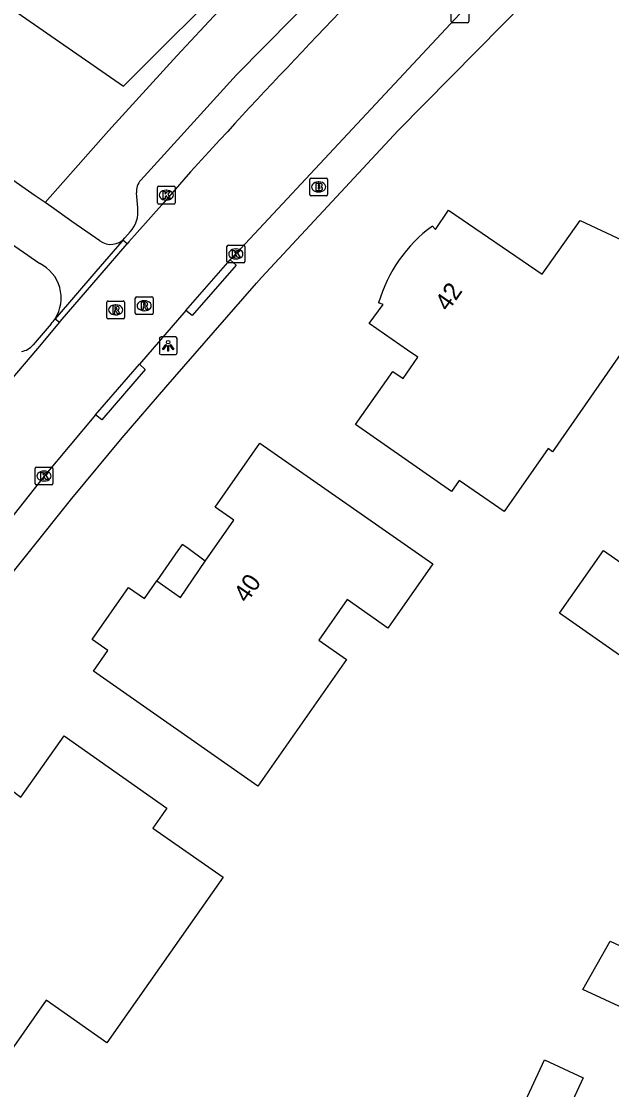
# Model space of a CAD drawing. Extents: x 158838 to 160074, y 386376 to 387776.
# Drawn here: x 159346.7 to 159380, y 386786.4 to 386846.6 of the extents above; entities that cross this region are included whole.
import ezdxf

# ---------------------------------------------------------------- set-up
doc = ezdxf.new("R2010")
doc.units = 0
for name, color, linetype in [('IMGEO_Brandkraan', 7, 'Continuous'), ('IMGEO_Kolk', 7, 'Continuous'), ('IMGEO_Lichtpunt', 7, 'Continuous'), ('IMGEO_Loofbos', 7, 'Continuous'), ('IMGEO_Muur', 7, 'Continuous'), ('IMGEO_Pand', 7, 'Continuous'), ('IMGEO_Pand_nummerreeks', 7, 'Continuous'), ('IMGEO_Pand_overbouw', 7, 'Continuous'), ('IMGEO_Rijbaan_lokaal_gesloten', 7, 'Continuous'), ('IMGEO_Rijbaan_lokaal_open', 7, 'Continuous'), ('IMGEO_Rioolput', 7, 'Continuous'), ('IMGEO_Voetpad_open', 7, 'Continuous')]:
    doc.layers.add(name, color=color, linetype=linetype)

msp = doc.modelspace()

# ---------------------------------------------------------------- linework, layer by layer
at = {"layer": 'IMGEO_Brandkraan'}
for p, q in [((159362.987, 386836.864), (159362.987, 386837.716)), ((159363.062, 386837.79), (159363.914, 386837.79)), ((159363.475, 386837.57), (159363.5, 386837.57)), ((159363.988, 386837.716), (159363.988, 386836.864)), ((159363.498, 386837.01), (159363.473, 386837.01)), ((159363.914, 386836.79), (159363.062, 386836.79))]:
    msp.add_line(p, q, dxfattribs=at)
for points in [[(159362.987, 386836.864), (159362.987, 386837.716)], [(159363.062, 386837.79), (159363.914, 386837.79)], [(159363.335, 386837.49), (159363.335, 386837.09), (159363.548, 386837.09)], [(159363.566, 386837.49), (159363.335, 386837.49)], [(159363.988, 386837.716), (159363.988, 386836.864)], [(159363.514, 386837.409), (159363.46, 386837.409), (159363.46, 386837.333)], [(159363.46, 386837.333), (159363.513, 386837.333)], [(159363.522, 386837.257), (159363.46, 386837.257), (159363.46, 386837.176)], [(159363.46, 386837.176), (159363.522, 386837.176)], [(159363.914, 386836.79), (159363.062, 386836.79)]]:
    msp.add_lwpolyline(points, dxfattribs=at)
for centre, radius, start, end in [((159363.064, 386837.714), 0.0765, 91.55205, 178.44795), ((159363.064, 386837.714), 0.0765, 91.55205, 178.44795), ((159363.57, 386837.345), 0.145, 59.4692, 91.53667), ((159363.595, 386837.392), 0.0922, 285.51372, 58.15012), ((159363.912, 386837.714), 0.0765, 1.55205, 88.44795), ((159363.912, 386837.714), 0.0765, 1.55205, 88.44795), ((159363.064, 386836.866), 0.0765, 181.55205, 268.44795), ((159363.064, 386836.866), 0.0765, 181.55205, 268.44795), ((159363.515, 386837.371), 0.0379, 267.82845, 90.93552), ((159363.523, 386837.216), 0.0404, 269.87594, 90.50774), ((159363.554, 386837.341), 0.251, 268.66757, 293.53466), ((159363.6, 386837.2), 0.105, 301.31148, 78.98903), ((159363.912, 386836.866), 0.0765, 271.55205, 358.44795), ((159363.912, 386836.866), 0.0765, 271.55205, 358.44795)]:
    msp.add_arc(centre, radius, start, end, dxfattribs=at)
for centre, major_axis, ratio, start_param, end_param in [((159363.474, 386837.29), (-0.387, 0.002), 0.722429, 4.712389, 7.853982), ((159363.499, 386837.29), (-0.39, 0.002), 0.717154, 1.570796, 4.712389)]:
    msp.add_ellipse(centre, major_axis=major_axis, ratio=ratio, start_param=start_param, end_param=end_param, dxfattribs=at)
at = {"layer": 'IMGEO_Kolk'}
for p, q in [((159370.953, 386846.626), (159370.953, 386847.478)), ((159371.954, 386847.478), (159371.954, 386846.626)), ((159371.88, 386846.552), (159371.028, 386846.552)), ((159354.395, 386836.402), (159354.395, 386837.254)), ((159354.47, 386837.328), (159355.322, 386837.328)), ((159354.883, 386837.108), (159354.908, 386837.108)), ((159355.396, 386837.254), (159355.396, 386836.402)), ((159355.322, 386836.328), (159354.47, 386836.328)), ((159354.906, 386836.548), (159354.881, 386836.548)), ((159358.319, 386833.089), (159358.319, 386833.941)), ((159358.394, 386834.015), (159359.246, 386834.015)), ((159359.32, 386833.941), (159359.32, 386833.089)), ((159358.83, 386833.235), (159358.805, 386833.235)), ((159358.807, 386833.795), (159358.832, 386833.795)), ((159359.246, 386833.015), (159358.394, 386833.015)), ((159347.51, 386820.564), (159347.51, 386821.416)), ((159347.585, 386821.49), (159348.437, 386821.49)), ((159347.998, 386821.27), (159348.023, 386821.27)), ((159348.511, 386821.416), (159348.511, 386820.564)), ((159348.021, 386820.71), (159347.996, 386820.71)), ((159348.437, 386820.49), (159347.585, 386820.49))]:
    msp.add_line(p, q, dxfattribs=at)
for points in [[(159370.953, 386846.626), (159370.953, 386847.478)], [(159371.954, 386847.478), (159371.954, 386846.626)], [(159371.88, 386846.552), (159371.028, 386846.552)], [(159354.395, 386836.402), (159354.395, 386837.254)], [(159354.47, 386837.328), (159355.322, 386837.328)], [(159354.716, 386837.028), (159354.839, 386837.028), (159354.839, 386836.877), (159354.969, 386837.028), (159355.133, 386837.028), (159354.987, 386836.877), (159355.14, 386836.628), (159354.988, 386836.628), (159354.903, 386836.792), (159354.839, 386836.725), (159354.839, 386836.628), (159354.716, 386836.628), (159354.716, 386837.028)], [(159355.396, 386837.254), (159355.396, 386836.402)], [(159355.322, 386836.328), (159354.47, 386836.328)], [(159358.319, 386833.089), (159358.319, 386833.941)], [(159358.394, 386834.015), (159359.246, 386834.015)], [(159359.32, 386833.941), (159359.32, 386833.089)], [(159358.64, 386833.715), (159358.763, 386833.715), (159358.763, 386833.564), (159358.893, 386833.715), (159359.057, 386833.715), (159358.911, 386833.564), (159359.064, 386833.315), (159358.912, 386833.315), (159358.827, 386833.479), (159358.763, 386833.412), (159358.763, 386833.315), (159358.64, 386833.315), (159358.64, 386833.715)], [(159359.246, 386833.015), (159358.394, 386833.015)], [(159347.51, 386820.564), (159347.51, 386821.416)], [(159347.585, 386821.49), (159348.437, 386821.49)], [(159347.831, 386821.19), (159347.954, 386821.19), (159347.954, 386821.039), (159348.084, 386821.19), (159348.248, 386821.19), (159348.102, 386821.039), (159348.255, 386820.79), (159348.103, 386820.79), (159348.018, 386820.954), (159347.954, 386820.887), (159347.954, 386820.79), (159347.831, 386820.79), (159347.831, 386821.19)], [(159348.511, 386821.416), (159348.511, 386820.564)], [(159348.437, 386820.49), (159347.585, 386820.49)]]:
    msp.add_lwpolyline(points, dxfattribs=at)
for centre, start, end in [((159371.03, 386846.628), 181.55205, 268.44795), ((159371.03, 386846.628), 181.55205, 268.44795), ((159371.878, 386846.628), 271.55205, 358.44795), ((159371.878, 386846.628), 271.55205, 358.44795), ((159354.472, 386837.252), 91.55205, 178.44795), ((159354.472, 386837.252), 91.55205, 178.44795), ((159355.32, 386837.252), 1.55205, 88.44795), ((159355.32, 386837.252), 1.55205, 88.44795), ((159354.472, 386836.404), 181.55205, 268.44795), ((159354.472, 386836.404), 181.55205, 268.44795), ((159355.32, 386836.404), 271.55205, 358.44795), ((159355.32, 386836.404), 271.55205, 358.44795), ((159358.396, 386833.939), 91.55205, 178.44795), ((159358.396, 386833.939), 91.55205, 178.44795), ((159359.244, 386833.939), 1.55205, 88.44795), ((159359.244, 386833.939), 1.55205, 88.44795), ((159358.396, 386833.091), 181.55205, 268.44795), ((159358.396, 386833.091), 181.55205, 268.44795), ((159359.244, 386833.091), 271.55205, 358.44795), ((159359.244, 386833.091), 271.55205, 358.44795), ((159347.587, 386821.414), 91.55205, 178.44795), ((159347.587, 386821.414), 91.55205, 178.44795), ((159348.435, 386821.414), 1.55205, 88.44795), ((159348.435, 386821.414), 1.55205, 88.44795), ((159347.587, 386820.566), 181.55205, 268.44795), ((159347.587, 386820.566), 181.55205, 268.44795), ((159348.435, 386820.566), 271.55205, 358.44795), ((159348.435, 386820.566), 271.55205, 358.44795)]:
    msp.add_arc(centre, 0.0765, start, end, dxfattribs=at)
for centre, major_axis, ratio, start_param, end_param in [((159354.882, 386836.828), (-0.387, 0.002), 0.722429, 4.712389, 7.853982), ((159354.907, 386836.828), (-0.39, 0.002), 0.717154, 1.570796, 4.712389), ((159358.806, 386833.515), (-0.387, 0.002), 0.722429, 4.712389, 7.853982), ((159358.831, 386833.515), (-0.39, 0.002), 0.717154, 1.570796, 4.712389), ((159347.997, 386820.99), (-0.387, 0.002), 0.722429, 4.712389, 7.853982), ((159348.022, 386820.99), (-0.39, 0.002), 0.717154, 1.570796, 4.712389)]:
    msp.add_ellipse(centre, major_axis=major_axis, ratio=ratio, start_param=start_param, end_param=end_param, dxfattribs=at)
at = {"layer": 'IMGEO_Lichtpunt'}
for p, q in [((159354.507, 386828.74), (159354.507, 386827.933)), ((159354.507, 386828.74), (159354.507, 386827.933)), ((159355.409, 386828.835), (159354.601, 386828.835)), ((159355.409, 386828.835), (159354.601, 386828.835)), ((159355.503, 386827.933), (159355.503, 386828.74)), ((159355.503, 386827.933), (159355.503, 386828.74)), ((159354.601, 386827.839), (159355.409, 386827.839)), ((159354.601, 386827.839), (159355.409, 386827.839))]:
    msp.add_line(p, q, dxfattribs=at)
for points in [[(159354.881, 386828.404), (159354.92, 386828.376), (159354.732, 386828.114), (159354.694, 386828.141), (159354.881, 386828.404)], [(159355.093, 386828.376), (159355.131, 386828.403), (159355.318, 386828.141), (159355.279, 386828.113), (159355.093, 386828.376)], [(159354.983, 386828.356), (159355.03, 386828.356), (159355.03, 386828.034), (159354.983, 386828.034), (159354.983, 386828.356)]]:
    msp.add_lwpolyline(points, dxfattribs=at)
msp.add_circle((159355.006, 386828.538), 0.0994, dxfattribs=at)
for centre, start, end in [((159354.601, 386828.74), 90, 180), ((159354.601, 386828.74), 90, 180), ((159355.409, 386828.74), 0, 90), ((159355.409, 386828.74), 0, 90), ((159354.601, 386827.933), 180, 270), ((159354.601, 386827.933), 180, 270), ((159355.409, 386827.933), 270, 0), ((159355.409, 386827.933), 270, 360)]:
    msp.add_arc(centre, 0.0946, start, end, dxfattribs=at)
at = {"layer": 'IMGEO_Loofbos'}
msp.add_lwpolyline([(159319.86, 386879.903), (159320.612, 386865.073), (159352.478, 386842.965), (159378.408, 386868.854), (159378.721, 386868.185)], dxfattribs=at)
at = {"layer": 'IMGEO_Muur'}
msp.add_lwpolyline([(159367.963, 386840.464), (159376.841, 386849.467)], dxfattribs=at)
at = {"layer": 'IMGEO_Pand'}
for points in [[(159369.894, 386835.087), (159370.064, 386834.895), (159370.797, 386835.972), (159376.087, 386832.37), (159378.221, 386835.389), (159383.598, 386832.874), (159380.865, 386828.941), (159381.127, 386828.758), (159376.676, 386822.354), (159376.414, 386822.537), (159373.943, 386818.981), (159371.414, 386820.739)], [(159371.414, 386820.739), (159370.98, 386820.115), (159365.571, 386823.897), (159367.664, 386826.89), (159368.246, 386826.483), (159369.084, 386827.687), (159368.487, 386828.092), (159366.338, 386829.584), (159367.116, 386830.671), (159366.867, 386830.758)], [(159350.799, 386809.989), (159351.611, 386811.149), (159350.73, 386811.779), (159352.772, 386814.696), (159353.667, 386814.077), (159354.358, 386815.082), (159355.707, 386814.149), (159357.093, 386816.188), (159358.709, 386818.504), (159357.65, 386819.243), (159360.17, 386822.851), (159369.926, 386816.037), (159367.394, 386812.419), (159365.096, 386814.027), (159363.494, 386811.738), (159365.053, 386810.647), (159360.057, 386803.509), (159350.799, 386809.989)], [(159377.062, 386813.258), (159379.538, 386816.799), (159388.236, 386810.717), (159385.76, 386807.176), (159377.062, 386813.258)], [(159348.121, 386791.432), (159346.166, 386788.643), (159339.205, 386793.521), (159340.111, 386794.826), (159337.819, 386796.435), (159338.772, 386797.786), (159338.646, 386798.547), (159340.146, 386800.672), (159340.907, 386800.815), (159341.839, 386802.169), (159344.145, 386800.581), (159344.645, 386801.267), (159345.06, 386800.944), (159346.084, 386802.421), (159345.63, 386802.742), (159346.086, 386803.344), (159346.699, 386802.879), (159349.135, 386806.346), (159354.936, 386802.269), (159354.145, 386801.14), (159358.104, 386798.365), (159351.556, 386789.024), (159348.121, 386791.432)], [(159382.177, 386785.015), (159384.19, 386789.348), (159378.376, 386792.048), (159379.917, 386794.772), (159398.425, 386786.098), (159398.32, 386781.418), (159403.148, 386781.277), (159403.134, 386780.811), (159403.01, 386776.578), (159402.926, 386773.733), (159402.789, 386768.951), (159392.853, 386769.235), (159392.862, 386769.535), (159390.653, 386769.598), (159390.781, 386774.106), (159392.99, 386774.043), (159393.239, 386782.749), (159387.934, 386785.213), (159386.837, 386782.851), (159382.177, 386785.015)], [(159376.216, 386788.076), (159378.392, 386787.066), (159377.184, 386784.464), (159375.008, 386785.475), (159376.216, 386788.076)]]:
    msp.add_lwpolyline(points, dxfattribs=at)
msp.add_arc((159374.793, 386828.439), 8.258, 126.38511, 163.6895, dxfattribs=at)
at = {"layer": 'IMGEO_Pand_overbouw'}
msp.add_lwpolyline([(159354.358, 386815.082), (159355.707, 386814.149), (159357.093, 386816.188), (159356.049, 386816.967), (159355.791, 386817.138), (159355.557, 386816.786)], close=True, dxfattribs=at)
at = {"layer": 'IMGEO_Rijbaan_lokaal_gesloten'}
for points in [[(159348.071, 386836.413), (159347.517, 386836.798), (159344.416, 386838.941), (159307.406, 386864.787), (159305.861, 386865.949), (159304.548, 386867.085), (159303.561, 386868.051), (159299.868, 386872.469), (159298.46, 386874.072)], [(159384.359, 386859.762), (159383.918, 386859.339), (159371.453, 386847.053), (159358.819, 386833.516), (159358.506, 386833.178)], [(159356.257, 386838.134), (159354.646, 386836.288), (159353.266, 386834.723), (159352.795, 386834.203), (159352.691, 386834.082)], [(159351.157, 386834.26), (159349.574, 386835.336), (159348.45, 386836.149), (159348.071, 386836.413)], [(159346.115, 386834.115), (159346.605, 386833.773), (159347.764, 386832.974)], [(159352.452, 386834.284), (159352.387, 386834.206), (159350.928, 386832.529), (159348.63, 386829.862)], [(159348.883, 386829.666), (159348.92, 386829.709), (159351.169, 386832.319), (159352.691, 386834.082)], [(159352.452, 386834.284), (159352.556, 386834.416)], [(159356.002, 386830.32), (159358.506, 386833.178)], [(159356.002, 386830.32), (159353.391, 386827.292)], [(159348.883, 386829.666), (159347.634, 386828.186), (159346.143, 386826.416), (159343.916, 386823.741), (159341.697, 386821.059), (159340.52, 386819.528), (159339.334, 386817.99), (159338.147, 386816.452), (159336.959, 386814.916), (159334.682, 386811.982), (159332.4, 386809.052)], [(159350.907, 386824.436), (159353.391, 386827.292)], [(159350.907, 386824.436), (159348.009, 386820.99), (159340.883, 386811.963)]]:
    msp.add_lwpolyline(points, dxfattribs=at)
for centre, radius, start, end in [((159712.384, 386513.677), 481.766, 135.31774, 137.66428), ((159351.776, 386835.059), 1.011, 232.21803, 320.5073), ((159346.808, 386831.031), 2.165, 327.30875, 63.79264)]:
    msp.add_arc(centre, radius, start, end, dxfattribs=at)
at = {"layer": 'IMGEO_Rijbaan_lokaal_open'}
for points in [[(159352.691, 386834.082), (159352.452, 386834.284)], [(159348.63, 386829.862), (159348.883, 386829.666)]]:
    msp.add_lwpolyline(points, dxfattribs=at)
at = {"layer": 'IMGEO_Rioolput'}
for p, q in [((159351.621, 386830.859), (159352.473, 386830.859)), ((159353.153, 386830.167), (159353.153, 386831.019)), ((159353.228, 386831.093), (159354.08, 386831.093)), ((159353.641, 386830.873), (159353.666, 386830.873)), ((159354.154, 386831.019), (159354.154, 386830.167)), ((159351.546, 386829.933), (159351.546, 386830.785)), ((159352.034, 386830.639), (159352.059, 386830.639)), ((159352.547, 386830.785), (159352.547, 386829.933)), ((159353.664, 386830.313), (159353.639, 386830.313)), ((159352.473, 386829.859), (159351.621, 386829.859)), ((159352.057, 386830.079), (159352.032, 386830.079)), ((159354.08, 386830.093), (159353.228, 386830.093))]:
    msp.add_line(p, q, dxfattribs=at)
for points in [[(159351.621, 386830.859), (159352.473, 386830.859)], [(159353.153, 386830.167), (159353.153, 386831.019)], [(159353.228, 386831.093), (159354.08, 386831.093)], [(159354.154, 386831.019), (159354.154, 386830.167)], [(159351.546, 386829.933), (159351.546, 386830.785)], [(159352.135, 386830.557), (159351.883, 386830.559), (159351.883, 386830.159)], [(159351.883, 386830.159), (159352.007, 386830.159), (159352.007, 386830.321), (159352.018, 386830.321)], [(159352.061, 386830.478), (159352.007, 386830.478), (159352.007, 386830.397)], [(159352.007, 386830.397), (159352.059, 386830.397)], [(159352.065, 386830.292), (159352.136, 386830.159), (159352.276, 386830.159), (159352.211, 386830.285)], [(159352.547, 386830.785), (159352.547, 386829.933)], [(159353.742, 386830.791), (159353.49, 386830.793), (159353.49, 386830.393)], [(159353.49, 386830.393), (159353.614, 386830.393), (159353.614, 386830.555), (159353.625, 386830.555)], [(159353.668, 386830.712), (159353.614, 386830.712), (159353.614, 386830.631)], [(159353.614, 386830.631), (159353.666, 386830.631)], [(159353.672, 386830.526), (159353.743, 386830.393), (159353.883, 386830.393), (159353.818, 386830.519)], [(159352.473, 386829.859), (159351.621, 386829.859)], [(159354.08, 386830.093), (159353.228, 386830.093)]]:
    msp.add_lwpolyline(points, dxfattribs=at)
for centre, radius, start, end in [((159351.623, 386830.783), 0.0765, 91.55205, 178.44795), ((159351.623, 386830.783), 0.0765, 91.55205, 178.44795), ((159352.471, 386830.783), 0.0765, 1.55205, 88.44795), ((159352.471, 386830.783), 0.0765, 1.55205, 88.44795), ((159353.23, 386831.017), 0.0765, 91.55205, 178.44795), ((159353.23, 386831.017), 0.0765, 91.55205, 178.44795), ((159354.078, 386831.017), 0.0765, 1.55205, 88.44795), ((159354.078, 386831.017), 0.0765, 1.55205, 88.44795), ((159352.017, 386830.268), 0.0533, 26.02933, 88.69889), ((159352.043, 386830.586), 0.19, 274.7715, 282.96867), ((159352.067, 386830.382), 0.0964, 77.00612, 93.18647), ((159352.081, 386830.439), 0.0378, 276.66336, 79.67722), ((159352.134, 386830.447), 0.109, 350.36119, 89.41601), ((159352.132, 386830.447), 0.112, 277.58423, 350.98172), ((159352.116, 386830.232), 0.108, 29.51342, 73.79051), ((159353.624, 386830.502), 0.0533, 26.02933, 88.69889), ((159353.65, 386830.82), 0.19, 274.7715, 282.96867), ((159353.674, 386830.616), 0.0964, 77.00612, 93.18647), ((159353.688, 386830.673), 0.0378, 276.66336, 79.67722), ((159353.741, 386830.681), 0.109, 350.36119, 89.41601), ((159353.739, 386830.681), 0.112, 277.58423, 350.98172), ((159353.723, 386830.466), 0.108, 29.51342, 73.79051), ((159351.623, 386829.935), 0.0765, 181.55205, 268.44795), ((159351.623, 386829.935), 0.0765, 181.55205, 268.44795), ((159352.471, 386829.935), 0.0765, 271.55205, 358.44795), ((159352.471, 386829.935), 0.0765, 271.55205, 358.44795), ((159353.23, 386830.169), 0.0765, 181.55205, 268.44795), ((159353.23, 386830.169), 0.0765, 181.55205, 268.44795), ((159354.078, 386830.169), 0.0765, 271.55205, 358.44795), ((159354.078, 386830.169), 0.0765, 271.55205, 358.44795)]:
    msp.add_arc(centre, radius, start, end, dxfattribs=at)
for centre, major_axis, ratio, start_param, end_param in [((159353.64, 386830.593), (-0.387, 0.002), 0.722429, 4.712389, 7.853982), ((159353.665, 386830.593), (-0.39, 0.002), 0.717154, 1.570796, 4.712389), ((159352.033, 386830.359), (-0.387, 0.002), 0.722429, 4.712389, 7.853982), ((159352.058, 386830.359), (-0.39, 0.002), 0.717154, 1.570796, 4.712389)]:
    msp.add_ellipse(centre, major_axis=major_axis, ratio=ratio, start_param=start_param, end_param=end_param, dxfattribs=at)
at = {"layer": 'IMGEO_Voetpad_open'}
for points in [[(159353.458, 386837.675), (159355.53, 386839.954), (159358.854, 386843.619), (159379.572, 386864.609)], [(159316.126, 386772.648), (159317.633, 386775.122), (159319.614, 386778.311), (159319.861, 386778.699), (159320.11, 386779.086), (159332.731, 386797.78), (159338.763, 386805.976), (159342.557, 386810.947), (159349.576, 386819.722), (159352.408, 386823.136), (159354.876, 386826.001), (159357.532, 386829.072), (159359.977, 386831.86), (159360.256, 386832.178), (159367.963, 386840.464), (159376.841, 386849.467), (159376.759, 386849.577), (159385.976, 386858.576)], [(159351.64, 386840.448), (159348.071, 386836.413)], [(159353.286, 386836.108), (159353.215, 386836.957)], [(159352.556, 386834.416), (159352.854, 386834.751)], [(159358.506, 386833.178), (159358.829, 386832.882), (159356.365, 386830.046), (159356.002, 386830.32)], [(159348.406, 386829.571), (159347.392, 386828.395)], [(159353.391, 386827.292), (159353.717, 386826.997), (159351.273, 386824.153), (159350.907, 386824.436)]]:
    msp.add_lwpolyline(points, dxfattribs=at)
for centre, radius, start, end in [((159692.216, 386534.114), 458.075, 133.44475, 138.02999), ((159354.183, 386837.029), 0.971, 138.33098, 184.27326), ((159351.676, 386835.873), 1.627, 316.38631, 8.29602), ((159346.74, 386831.085), 2.252, 317.73469, 327.09008), ((159346.617, 386828.988), 0.976, 276.70011, 322.56537)]:
    msp.add_arc(centre, radius, start, end, dxfattribs=at)

# ---------------------------------------------------------------- texts
at = {"layer": 'IMGEO_Pand_nummerreeks'}
for s, rotation, p in [('42', 55.0839, (159370.782, 386830.221)), ('40', 55.42063, (159359.442, 386813.787))]:
    msp.add_text(s, height=1, rotation=rotation, dxfattribs=at).set_placement(p)

doc.saveas('drawing.dxf')
